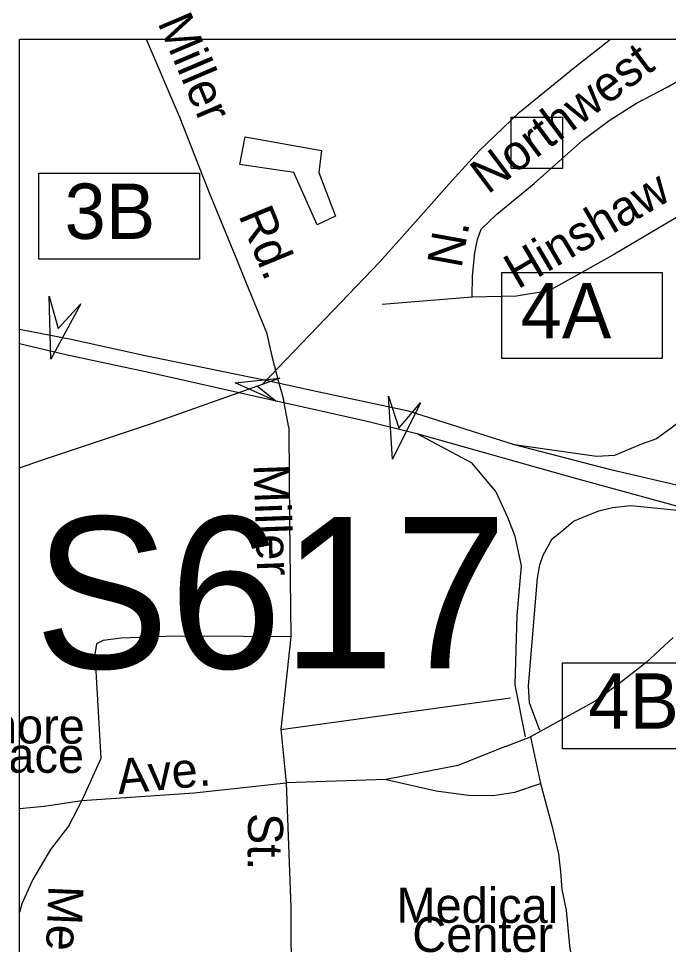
# Model space of a CAD drawing. Extents: x 1553981 to 1780076, y 812965 to 996873.
# Drawn here: x 1632322.7 to 1632542.8, y 847849 to 848162.4 of the extents above; entities that cross this region are included whole.
import ezdxf

# ---------------------------------------------------------------- set-up
doc = ezdxf.new("R2010")
doc.units = 0
for name, color, linetype in [('Default', 7, 'Continuous'), ('Exist Civil Correctional or Penal Institution CELL', 7, 'Continuous'), ('Exist Cultural Church with Cemetery CELL', 7, 'Continuous'), ('Exist Cultural School High CELL', 7, 'Continuous'), ('Exist Cultural Warehouse Building Footprint', 7, 'Continuous'), ('Exist Railroad Mainline', 7, 'Continuous'), ('Exist Road Non-System Structure Non-Sys Other CELL', 7, 'Continuous'), ('Exist Road Non-System Type 51 Label', 7, 'Continuous'), ('Exist Road Primary Interstate Divided Center Attributed', 7, 'Continuous'), ('Exist Road Primary Interstate Ramp 1 Lane Attributed', 7, 'Continuous'), ('Exist Road Primary Interstate Structure Ovrhead Sign Number Label', 7, 'Continuous'), ('Exist Road Secondary Structure Standard Bridge Attributed CELL', 7, 'Continuous'), ('Map Preparation Border County Name Lower Right Label', 7, 'Continuous')]:
    doc.layers.add(name, color=color, linetype=linetype)

msp = doc.modelspace()

# ---------------------------------------------------------------- linework, layer by layer
at = {"layer": 'Default'}
msp.add_lwpolyline([(1632323.05, 848155.4), (1636375.85, 848155.4), (1636375.85, 845052.3), (1632323.05, 845052.3)], close=True, dxfattribs=at)
at = {"layer": 'Exist Civil Correctional or Penal Institution CELL'}
for points in [[(1632329.63, 848110.11), (1632384, 848110.11), (1632384, 848080.96), (1632329.63, 848080.96)], [(1632486.31, 848076.45), (1632540.67, 848076.45), (1632540.67, 848047.3), (1632486.31, 848047.3)], [(1632506.92, 847944.31), (1632561.29, 847944.31), (1632561.29, 847915.15), (1632506.92, 847915.15)]]:
    msp.add_lwpolyline(points, close=True, dxfattribs=at)
at = {"layer": 'Exist Cultural Church with Cemetery CELL'}
msp.add_lwpolyline([(1632343.81, 848065.84), (1632333.62, 848047.1), (1632333.07, 848068.43), (1632336.11, 848057.47)], close=True, dxfattribs=at)
at = {"layer": 'Exist Cultural School High CELL'}
msp.add_lwpolyline([(1632458.82, 848032.37), (1632449.29, 848013.28), (1632448, 848034.58), (1632451.42, 848023.73)], close=True, dxfattribs=at)
at = {"layer": 'Exist Cultural Warehouse Building Footprint'}
msp.add_lwpolyline([(1632399.49, 848122.39), (1632425.26, 848117.81), (1632424.43, 848110.32), (1632430.04, 848095.55), (1632423.8, 848092.64), (1632415.91, 848110.32), (1632397.62, 848113.03)], close=True, dxfattribs=at)
at = {"layer": 'Exist Railroad Mainline'}
msp.add_lwpolyline([(1632323.05, 848010.29), (1632330.47, 848012.89), (1632368.47, 848025.56), (1632405.31, 848038.66), (1632445.04, 848080.07), (1632458.97, 848095.64), (1632469.36, 848107.49), (1632478.72, 848117.63), (1632492.37, 848130.68), (1632511.07, 848145.94), (1632523.12, 848155.4)], dxfattribs=at)
at = {"layer": 'Exist Road Non-System Structure Non-Sys Other CELL'}
msp.add_lwpolyline([(1632489.53, 848129.08), (1632506.9, 848129.08), (1632506.9, 848111.7), (1632489.53, 848111.7)], close=True, dxfattribs=at)
at = {"layer": 'Exist Road Primary Interstate Divided Center Attributed'}
for points in [[(1632406.48, 848039.88), (1632396.52, 848041.87), (1632365.61, 848048.27), (1632340.56, 848053.78), (1632323.07, 848057.19), (1632323.05, 848057.2)], [(1632323.05, 848052.39), (1632338.74, 848048.69), (1632367.26, 848042.62), (1632396.89, 848035.97)], [(1632490.68, 848018.16), (1632454.77, 848029.56), (1632424.46, 848035.9), (1632406.48, 848039.88)], [(1632396.89, 848035.97), (1632440.25, 848026.28), (1632457.54, 848021.99)], [(1632457.54, 848021.99), (1632511.57, 848006.66), (1632553.71, 847995.23)], [(1632579.76, 847996.41), (1632523.27, 848009.59), (1632490.68, 848018.16)]]:
    msp.add_lwpolyline(points, dxfattribs=at)
at = {"layer": 'Exist Road Primary Interstate Ramp 1 Lane Attributed'}
for points in [[(1632641.66, 848031.21), (1632599.46, 848040.52), (1632583.01, 848044.1), (1632579.08, 848044.81), (1632575.14, 848044.81), (1632572.28, 848044.1), (1632569.42, 848043.02), (1632566.92, 848041.59), (1632560.84, 848037.3), (1632548.68, 848027.64), (1632543.67, 848023.7), (1632538.66, 848020.12), (1632533.65, 848018.33), (1632524.45, 848014.51), (1632518.37, 848014.16), (1632490.68, 848018.16)], [(1632457.54, 848021.99), (1632476.01, 848012.17), (1632484.3, 848002.23), (1632488.23, 847993.64), (1632490.74, 847987.2), (1632492.88, 847977.18), (1632491.45, 847960.36), (1632490.73, 847936.9), (1632494.22, 847919.21)], [(1632499.2, 847921.45), (1632495.71, 847930.79), (1632495.34, 847936.52), (1632498.4, 847972.97), (1632499.22, 847977.51), (1632500.3, 847980.73), (1632503.41, 847986.34), (1632506.63, 847988.85), (1632510.61, 847992.24), (1632513.83, 847993.67), (1632519.21, 847995.8), (1632523.86, 847996.88), (1632530, 847997.58), (1632553.71, 847995.23)]]:
    msp.add_lwpolyline(points, dxfattribs=at)
at = {"layer": 'Exist Road Secondary Structure Standard Bridge Attributed CELL'}
msp.add_lwpolyline([(1632409.98, 848032.91), (1632396.07, 848039.14), (1632411.23, 848040.7), (1632403.59, 848037.93)], close=True, dxfattribs=at)
at = {"layer": 'Map Preparation Border County Name Lower Right Label'}
for p, q in [((1632476.27, 848068.13), (1632445.78, 848065.59)), ((1632408.51, 848048.1), (1632410.9, 848038.99)), ((1632410.9, 848038.99), (1632411.71, 848035.96)), ((1632411.71, 848035.96), (1632412.56, 848032.91)), ((1632414.19, 848023.96), (1632412.56, 848032.91)), ((1632414.86, 847953.16), (1632411.47, 847921.77)), ((1632411.47, 847921.77), (1632489.31, 847932.44)), ((1632411.47, 847921.77), (1632413.35, 847903.71)), ((1632496.1, 847919.2), (1632499.39, 847903.46)), ((1632447.2, 847904.84), (1632413.35, 847903.71))]:
    msp.add_line(p, q, dxfattribs=at)
for points in [[(1632365.98, 848155.4), (1632377.3, 848128.82), (1632387.38, 848103.2), (1632396.84, 848080.23), (1632398.47, 848076.28), (1632401.76, 848068.22), (1632406.66, 848056.18), (1632408.51, 848048.1)], [(1632476.27, 848068.13), (1632476.39, 848075.38), (1632477.25, 848083.11), (1632478.07, 848087.6), (1632479.36, 848091.08), (1632484.69, 848096.24), (1632497.33, 848106.54), (1632513.79, 848121.29), (1632522.63, 848127.92), (1632531.95, 848133.76), (1632542.52, 848139.35), (1632556.35, 848147.47)], [(1632585.09, 848118.02), (1632572.34, 848110.93), (1632546.87, 848095.81), (1632524.44, 848082.66), (1632509.84, 848074.37), (1632502.28, 848070.25), (1632491.26, 848068.42), (1632476.27, 848068.13)], [(1632414.19, 848023.96), (1632414.35, 848006.74), (1632414.49, 847992.48), (1632414.86, 847953.16)], [(1632414.86, 847953.16), (1632398.9, 847953.21), (1632375.69, 847953.3), (1632357.44, 847952.6), (1632351.42, 847951.92), (1632349.17, 847950.71), (1632348.6, 847947.22), (1632349.4, 847933.72), (1632350.59, 847911.96), (1632344.14, 847897.68)], [(1632544.38, 847952.84), (1632535.08, 847944.25), (1632525.79, 847937.09), (1632517.92, 847931.37), (1632496.1, 847919.2)], [(1632487.59, 847915.98), (1632496.1, 847919.2)], [(1632487.59, 847915.98), (1632471.49, 847909.54), (1632447.2, 847904.84)], [(1632344.14, 847897.68), (1632382.13, 847900.32), (1632413.35, 847903.71)], [(1632413.35, 847903.71), (1632414.89, 847861.64), (1632414.89, 847849.41), (1632415.64, 847828.52), (1632415.64, 847812.15)], [(1632447.2, 847904.84), (1632464.07, 847900.93), (1632475.05, 847899.51), (1632483.38, 847899.41), (1632490.78, 847900.54), (1632499.39, 847903.46)], [(1632499.39, 847903.46), (1632503.24, 847889.29), (1632505.51, 847879.62), (1632506.26, 847873.59), (1632506.64, 847867.57), (1632508.16, 847860.55)], [(1632323.05, 847894.94), (1632331.35, 847895.8), (1632344.14, 847897.68)], [(1632344.14, 847897.68), (1632339.62, 847889.03), (1632333.6, 847881.12), (1632327.59, 847870.96), (1632323.82, 847862.68), (1632323.05, 847859.79)], [(1632508.16, 847860.55), (1632509.29, 847848.45), (1632510.42, 847841.64), (1632511.56, 847837.48), (1632514.58, 847833.32), (1632516.85, 847829.92), (1632521.01, 847825.38)]]:
    msp.add_lwpolyline(points, dxfattribs=at)

# ---------------------------------------------------------------- texts
at = {"layer": 'Exist Civil Correctional or Penal Institution CELL'}
for s, p in [('3B', (1632338.32, 848087.82)), ('4A', (1632492.74, 848054.16)), ('4B', (1632515.61, 847922.01))]:
    msp.add_text(s, height=18.75, dxfattribs=at).set_placement(p)
at = {"layer": 'Exist Road Non-System Type 51 Label'}
for s, rotation, p in [('Miller', 293.0573, (1632369.65, 848161.1)), ('Northwest', 36.8499, (1632481.57, 848102.71)), ('Hinshaw', 30.388, (1632491.72, 848070.6)), ('Rd.', 292.3845, (1632397.05, 848095.89)), ('N.', 79.6836, (1632472.64, 848077.61)), ('Miller', 272.0938, (1632402.23, 848011.45)), ('Ardmore', 359.7631, (1632284.26, 847917.19)), ('Terrace', 359.7631, (1632290.16, 847907.25)), ('Ave.', 5.535, (1632356.59, 847899.83)), ('St.', 269.3672, (1632400.47, 847893.51)), ('Melrose', 267.6724, (1632332.91, 847869.07)), ('Medical', 359.8789, (1632450.67, 847856.34)), ('Center', 0.0174, (1632456.04, 847846.4))]:
    msp.add_text(s, height=11.875, rotation=rotation, dxfattribs=at).set_placement(p)
at = {"layer": 'Exist Road Primary Interstate Structure Ovrhead Sign Number Label'}
msp.add_text('S617', height=51.263, dxfattribs=at).set_placement((1632328.05, 847942.44))

doc.saveas('drawing.dxf')
